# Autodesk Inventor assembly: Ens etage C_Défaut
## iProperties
Shininess: 64.0
Length Units: 11269
Angle Units: 11279
Time Units: 11290
Mass Units: 11283
Length Display Precision: 3
Angle Display Precision: 2
Compacted: True
Created: 2006-01
Part Number: Ens etage C_Défaut
Document SubType Name: Assembly
Designer: Fricot
Density: 0.0
Volumn: 0.0
Area: 0.0
PropertySet Name: Model Information
Control State: 0
Master: False
Checked Out: False
Author: Fricot
